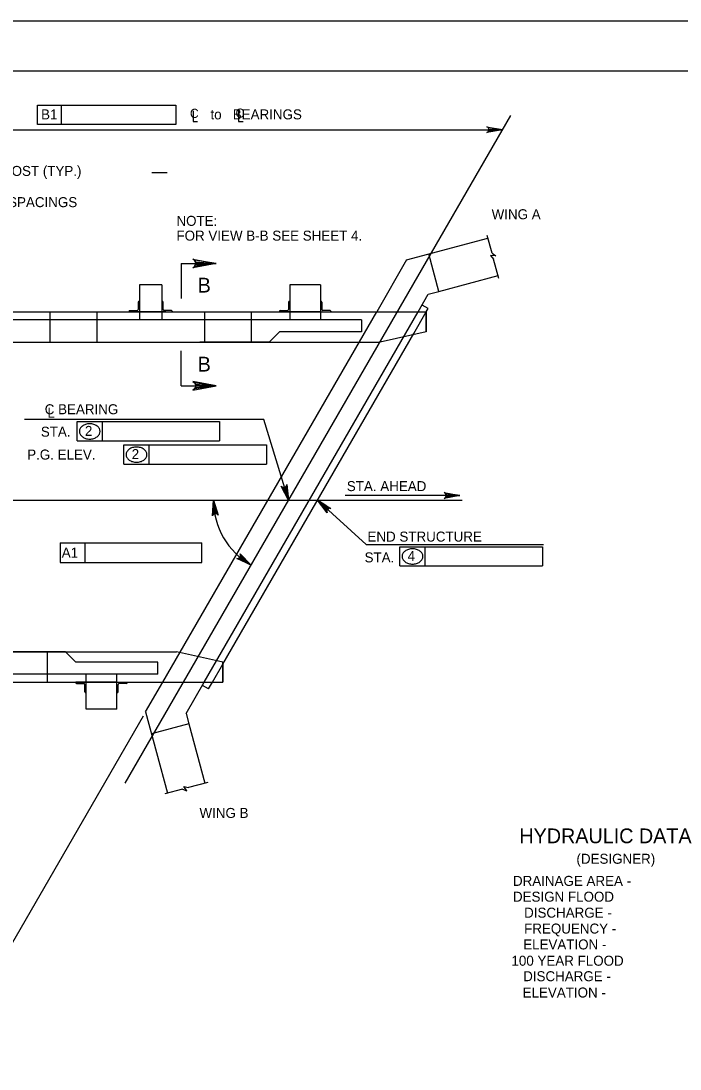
# Model space of a CAD drawing. Extents: x 638263 to 640391, y 293683 to 298655.
# Drawn here: x 638691.7 to 638889.5, y 298120.9 to 298435.5 of the extents above; entities that cross this region are included whole.
import ezdxf

# ---------------------------------------------------------------- set-up
doc = ezdxf.new("R2010")
doc.units = 0
for name, color, linetype in [('2', 7, 'Continuous'), ('3', 7, 'Continuous'), ('4', 7, 'Continuous'), ('PLT-BNDY', 7, 'Continuous')]:
    doc.layers.add(name, color=color, linetype=linetype)

msp = doc.modelspace()

# ---------------------------------------------------------------- linework, layer by layer
at = {"layer": '2'}
for p, q in [((638475.46, 298420.46), (639261.46, 298420.46)), ((638807.45, 298363.76), (638831.86, 298370.3)), ((638807.45, 298363.76), (638798.47, 298348.19)), ((638817.08, 298354.29), (638814.07, 298365.53)), ((638739.81, 298362.69), (638739.81, 298352.2)), ((638739.81, 298362.69), (638750.3, 298362.69)), ((638817.08, 298354.29), (638834.87, 298359.05)), ((638733.99, 298356.28), (638727.26, 298356.28)), ((638727.26, 298356.28), (638727.26, 298345.79)), ((638733.99, 298356.28), (638733.99, 298345.79)), ((638781.61, 298356.28), (638772.37, 298356.28)), ((638772.37, 298356.28), (638772.37, 298345.79)), ((638781.61, 298356.28), (638781.61, 298345.79)), ((638813.93, 298353.44), (638817.08, 298354.29)), ((638726.9, 298351.1), (638726.9, 298348.91)), ((638727.08, 298351.28), (638727.26, 298351.28)), ((638727.26, 298351.28), (638727.26, 298348.19)), ((638734.17, 298351.28), (638733.99, 298351.28)), ((638733.99, 298351.28), (638733.99, 298348.19)), ((638734.35, 298351.1), (638734.35, 298348.91)), ((638772.01, 298351.1), (638772.01, 298348.91)), ((638772.19, 298351.28), (638772.37, 298351.28)), ((638772.37, 298351.28), (638772.37, 298348.19)), ((638781.79, 298351.28), (638781.61, 298351.28)), ((638781.61, 298351.28), (638781.61, 298348.19)), ((638781.97, 298351.1), (638781.97, 298348.91)), ((638810.9, 298348.19), (638813.93, 298353.44)), ((638666.26, 298348.19), (638813.35, 298348.19)), ((638700.43, 298348.19), (638700.43, 298339.07)), ((638714.46, 298348.19), (638714.46, 298339.07)), ((638724.17, 298348.37), (638724.17, 298348.19)), ((638727.26, 298348.19), (638724.17, 298348.19)), ((638724.35, 298348.55), (638726.53, 298348.55)), ((638735.24, 298348.19), (638726.01, 298348.19)), ((638733.99, 298348.19), (638727.26, 298348.19)), ((638733.99, 298348.19), (638737.08, 298348.19)), ((638734.28, 298237.01), (638798.47, 298348.19)), ((638736.9, 298348.55), (638734.72, 298348.55)), ((638737.08, 298348.37), (638737.08, 298348.19)), ((638746.71, 298237.01), (638810.9, 298348.19)), ((638746.8, 298348.19), (638746.8, 298339.07)), ((638760.82, 298348.19), (638760.82, 298339.07)), ((638769.28, 298348.37), (638769.28, 298348.19)), ((638772.37, 298348.19), (638769.28, 298348.19)), ((638769.46, 298348.55), (638771.64, 298348.55)), ((638781.61, 298348.19), (638772.37, 298348.19)), ((638781.61, 298348.19), (638784.7, 298348.19)), ((638784.52, 298348.55), (638782.34, 298348.55)), ((638784.7, 298348.37), (638784.7, 298348.19)), ((638809.62, 298341.71), (638813.35, 298348.18)), ((638813.91, 298349.15), (638812.06, 298350.21)), ((638813.35, 298348.18), (638813.91, 298349.15)), ((638813.35, 298342.16), (638813.35, 298348.19)), ((638813.35, 298348.19), (638813.35, 298342.16)), ((638793.93, 298345.79), (638666.09, 298345.79)), ((638793.93, 298345.79), (638793.93, 298342.16)), ((638752.28, 298242.4), (638809.62, 298341.71)), ((638766.2, 298339.07), (638769.29, 298342.16)), ((638793.93, 298342.16), (638769.29, 298342.16)), ((638813.35, 298342.16), (638799.5, 298339.07)), ((638648.64, 298339.07), (638799.5, 298339.07)), ((638766.2, 298339.07), (638745.42, 298339.07)), ((638739.81, 298325.96), (638739.81, 298336.44)), ((638739.81, 298325.96), (638750.3, 298325.96)), ((638587.55, 298246.13), (638738.41, 298246.13)), ((638705.11, 298246.13), (638688.95, 298246.13)), ((638699.73, 298237.01), (638699.73, 298246.13)), ((638705.11, 298246.13), (638708.2, 298243.04)), ((638750.09, 298243.53), (638738.41, 298246.13)), ((638732.84, 298243.04), (638708.2, 298243.04)), ((638732.84, 298239.41), (638732.84, 298243.04)), ((638749.17, 298237.01), (638752.28, 298242.4)), ((638752.26, 298243.04), (638750.09, 298243.53)), ((638752.26, 298237.01), (638752.26, 298243.04)), ((638752.26, 298242.4), (638752.26, 298237.01)), ((638752.28, 298242.4), (638752.28, 298237.01)), ((638732.84, 298239.41), (638605, 298239.41)), ((638711.28, 298228.92), (638711.28, 298239.41)), ((638720.52, 298228.92), (638720.52, 298239.41)), ((638540.4, 298237.01), (638752.28, 298237.01)), ((638605.17, 298237.01), (638752.26, 298237.01)), ((638708.19, 298236.83), (638708.19, 298237.01)), ((638711.28, 298237.01), (638708.19, 298237.01)), ((638708.37, 298236.65), (638710.55, 298236.65)), ((638710.92, 298234.1), (638710.92, 298236.29)), ((638720.52, 298237.01), (638711.28, 298237.01)), ((638711.28, 298233.92), (638711.28, 298237.01)), ((638720.52, 298233.92), (638720.52, 298237.01)), ((638720.52, 298237.01), (638723.61, 298237.01)), ((638720.88, 298234.1), (638720.88, 298236.29)), ((638723.43, 298236.65), (638721.25, 298236.65)), ((638723.61, 298236.83), (638723.61, 298237.01)), ((638729.14, 298228.11), (638734.28, 298237.01)), ((638741.31, 298227.66), (638746.71, 298237.01)), ((638748, 298234.99), (638746.16, 298236.06)), ((638748, 298234.99), (638749.17, 298237.01)), ((638711.1, 298233.92), (638711.28, 298233.92)), ((638720.7, 298233.92), (638720.52, 298233.92)), ((638720.52, 298228.92), (638711.28, 298228.92)), ((638729.14, 298228.11), (638735.68, 298203.71)), ((638741.31, 298227.66), (638742.15, 298224.51)), ((638742.15, 298224.51), (638730.91, 298221.5)), ((638742.15, 298224.51), (638746.92, 298206.72))]:
    msp.add_line(p, q, dxfattribs=at)
for points in [[(638750.3, 298362.69), (638743.31, 298361.38), (638743.85, 298361.75), (638744.12, 298362.22), (638744.2, 298362.69), (638744.12, 298363.16), (638743.85, 298363.63), (638743.31, 298364), (638750.3, 298362.69), (638743.85, 298363.63), (638744.12, 298363.16), (638750.3, 298362.69), (638744.2, 298362.69), (638744.12, 298362.22), (638750.3, 298362.69), (638743.85, 298361.75)], [(638750.3, 298325.96), (638743.31, 298327.27), (638743.85, 298326.9), (638744.12, 298326.43), (638744.2, 298325.96), (638744.12, 298325.49), (638743.85, 298325.02), (638743.31, 298324.65), (638750.3, 298325.96), (638743.85, 298325.02), (638744.12, 298325.49), (638750.3, 298325.96), (638744.2, 298325.96), (638744.12, 298326.43), (638750.3, 298325.96), (638743.85, 298326.9)]]:
    msp.add_lwpolyline(points, dxfattribs=at)
for centre, radius, start, end in [((638727.08, 298351.1), 0.182, 90, 179.9984), ((638734.17, 298351.1), 0.182, 0.0016, 90), ((638772.19, 298351.1), 0.182, 90, 179.9984), ((638781.79, 298351.1), 0.182, 0.0016, 90), ((638724.35, 298348.37), 0.182, 90, 179.9984), ((638726.53, 298348.91), 0.364, 270, 359.9984), ((638734.72, 298348.91), 0.364, 180.0016, 270), ((638736.9, 298348.37), 0.182, 0.0016, 90), ((638769.46, 298348.37), 0.182, 90, 179.9984), ((638771.64, 298348.91), 0.364, 270, 359.9984), ((638782.34, 298348.91), 0.364, 180.0016, 270), ((638784.52, 298348.37), 0.182, 0.0016, 90), ((638708.37, 298236.83), 0.182, 180.0016, 270), ((638710.55, 298236.29), 0.364, 0.0016, 90), ((638721.25, 298236.29), 0.364, 90, 179.9984), ((638723.43, 298236.83), 0.182, 270, 359.9984), ((638711.1, 298234.1), 0.182, 180.0016, 270), ((638720.7, 298234.1), 0.182, 270, 359.9984)]:
    msp.add_arc(centre, radius, start, end, dxfattribs=at)
at = {"layer": '3'}
for p, q in [((638722.98, 298206.67), (638838.69, 298407.1)), ((638833.08, 298365.76), (638831.65, 298371.09)), ((638832.61, 298365.03), (638833.54, 298364.02)), ((638834.17, 298364.94), (638832.61, 298365.03)), ((638833.08, 298365.76), (638834.17, 298364.94)), ((638835.1, 298358.18), (638833.54, 298364.02)), ((638747.79, 298206.96), (638741.96, 298205.39)), ((638740.22, 298204.93), (638734.88, 298203.5)), ((638740.22, 298204.93), (638741.48, 298204.39)), ((638741.48, 298204.39), (638740.62, 298205.69)), ((638740.62, 298205.69), (638741.96, 298205.39))]:
    msp.add_line(p, q, dxfattribs=at)
at = {"layer": '4'}
for p, q in [((638696.71, 298410.17), (638703.94, 298410.17)), ((638696.71, 298404.4), (638696.71, 298410.17)), ((638703.94, 298404.4), (638703.94, 298410.17)), ((638703.94, 298410.17), (638738.23, 298410.17)), ((638738.23, 298410.17), (638738.23, 298404.4)), ((638743.4, 298408.45), (638743.4, 298405.26)), ((638757.04, 298408.45), (638757.04, 298405.26)), ((638738.23, 298404.4), (638696.71, 298404.4)), ((638743.4, 298405.26), (638744.73, 298405.26)), ((638757.04, 298405.26), (638758.38, 298405.26)), ((638644.81, 298402.81), (638836.22, 298402.81)), ((638731.01, 298389.95), (638735.65, 298389.95)), ((638764.57, 298315.83), (638692.76, 298315.83)), ((638708.59, 298315.21), (638716.16, 298315.21)), ((638708.59, 298309.44), (638708.59, 298315.21)), ((638716.16, 298309.44), (638716.16, 298315.21)), ((638716.16, 298315.21), (638751.35, 298315.21)), ((638751.35, 298315.21), (638751.35, 298309.44)), ((638772.04, 298291.65), (638764.57, 298315.83)), ((638708.59, 298309.44), (638751.35, 298309.44)), ((638722.63, 298308.24), (638730.2, 298308.24)), ((638722.63, 298302.47), (638722.63, 298308.24)), ((638730.2, 298302.47), (638730.2, 298308.24)), ((638730.2, 298308.24), (638765.39, 298308.24)), ((638765.39, 298308.24), (638765.39, 298302.47)), ((638722.63, 298302.47), (638765.39, 298302.47)), ((638539.12, 298291.65), (638824.14, 298291.65)), ((638780.71, 298291.65), (638795.32, 298278.31)), ((638823.37, 298293.05), (638789.02, 298293.05)), ((638703.46, 298278.86), (638703.45, 298272.96)), ((638703.46, 298278.86), (638711.02, 298278.86)), ((638711.02, 298272.96), (638711.02, 298278.86)), ((638711.02, 298278.86), (638745.98, 298278.86)), ((638745.98, 298272.96), (638745.98, 298278.86)), ((638795.32, 298278.31), (638848.5, 298278.31)), ((638805.42, 298277.69), (638813, 298277.69)), ((638805.42, 298271.92), (638805.42, 298277.69)), ((638813, 298271.92), (638813, 298277.69)), ((638813, 298277.69), (638848.18, 298277.69)), ((638848.18, 298277.69), (638848.18, 298271.92)), ((638703.45, 298272.96), (638745.98, 298272.96)), ((638805.42, 298271.92), (638848.18, 298271.92)), ((638728.37, 298226.78), (638683.43, 298148.94))]:
    msp.add_line(p, q, dxfattribs=at)
for points in [[(638836.22, 298402.81), (638831.56, 298401.94), (638831.92, 298402.19), (638832.1, 298402.5), (638832.15, 298402.81), (638832.1, 298403.12), (638831.92, 298403.44), (638831.56, 298403.68), (638836.22, 298402.81), (638831.92, 298403.44), (638832.1, 298403.12), (638836.22, 298402.81), (638832.15, 298402.81), (638832.1, 298402.5), (638836.22, 298402.81), (638831.92, 298402.19)], [(638772.04, 298291.65), (638769.83, 298295.84), (638770.17, 298295.57), (638770.52, 298295.49), (638770.84, 298295.53), (638771.12, 298295.67), (638771.37, 298295.94), (638771.5, 298296.36), (638772.04, 298291.65), (638771.37, 298295.94), (638771.12, 298295.67), (638772.04, 298291.65), (638770.84, 298295.53), (638770.52, 298295.49), (638772.04, 298291.65), (638770.17, 298295.57)], [(638749.5, 298291.65), (638750.93, 298287.13), (638750.64, 298287.45), (638750.31, 298287.6), (638749.99, 298287.61), (638749.69, 298287.52), (638749.4, 298287.3), (638749.2, 298286.92), (638749.5, 298291.65), (638749.4, 298287.3), (638749.69, 298287.52), (638749.5, 298291.65), (638749.99, 298287.61), (638750.31, 298287.6), (638749.5, 298291.65), (638750.64, 298287.45)], [(638780.71, 298291.65), (638784.74, 298289.15), (638784.31, 298289.21), (638783.96, 298289.1), (638783.71, 298288.91), (638783.54, 298288.64), (638783.47, 298288.28), (638783.56, 298287.86), (638780.71, 298291.65), (638783.47, 298288.28), (638783.54, 298288.64), (638780.71, 298291.65), (638783.71, 298288.91), (638783.96, 298289.1), (638780.71, 298291.65), (638784.31, 298289.21)], [(638823.37, 298293.05), (638818.71, 298292.18), (638819.07, 298292.43), (638819.26, 298292.74), (638819.31, 298293.05), (638819.26, 298293.36), (638819.07, 298293.68), (638818.71, 298293.92), (638823.37, 298293.05), (638819.07, 298293.68), (638819.26, 298293.36), (638823.37, 298293.05), (638819.31, 298293.05), (638819.26, 298292.74), (638823.37, 298293.05), (638819.07, 298292.43)], [(638760.77, 298272.13), (638756.48, 298274.15), (638756.91, 298274.14), (638757.24, 298274.28), (638757.47, 298274.51), (638757.61, 298274.79), (638757.64, 298275.15), (638757.5, 298275.56), (638760.77, 298272.13), (638757.64, 298275.15), (638757.61, 298274.79), (638760.77, 298272.13), (638757.47, 298274.51), (638757.24, 298274.28), (638760.77, 298272.13), (638756.91, 298274.14)]]:
    msp.add_lwpolyline(points, dxfattribs=at)
for points in [[(638771.64, 298294.61), (638770.69, 298294.32), (638772.04, 298291.65)], [(638782.56, 298289.29), (638783.22, 298290.02), (638780.71, 298291.65)]]:
    msp.add_lwpolyline(points, close=True, dxfattribs=at)
for centre, radius, start, end in [((638711.64, 298311.9), 2.49, 126.3544, 150.6308), ((638712.08, 298311.3), 3.23, 106.9552, 126.3544), ((638712.37, 298310.35), 4.22, 90, 106.9552), ((638712.37, 298310.35), 4.22, 73.0448, 90), ((638712.66, 298311.3), 3.23, 53.6456, 73.0448), ((638713.1, 298311.9), 2.49, 29.3692, 53.6456), ((638710.96, 298312.28), 1.71, 150.6308, 180), ((638710.96, 298312.28), 1.71, 180, 209.3692), ((638711.64, 298312.66), 2.49, 209.3692, 233.6456), ((638712.08, 298313.26), 3.23, 233.6456, 253.0448), ((638712.37, 298314.2), 4.22, 253.0448, 270), ((638712.37, 298314.2), 4.22, 270, 286.9552), ((638712.66, 298313.26), 3.23, 286.9552, 306.3544), ((638713.1, 298312.66), 2.49, 306.3544, 330.6308), ((638713.78, 298312.28), 1.71, 0, 29.3692), ((638713.78, 298312.28), 1.71, 330.6308, 0), ((638725.68, 298304.93), 2.49, 126.3544, 150.6308), ((638726.12, 298304.33), 3.23, 106.9552, 126.3544), ((638726.41, 298303.38), 4.22, 90, 106.9552), ((638726.41, 298303.38), 4.22, 73.0448, 90), ((638726.7, 298304.33), 3.23, 53.6456, 73.0448), ((638727.14, 298304.93), 2.49, 29.3692, 53.6456), ((638725, 298305.31), 1.71, 150.6308, 180), ((638725, 298305.31), 1.71, 180, 209.3692), ((638725.68, 298305.69), 2.49, 209.3692, 233.6456), ((638727.14, 298305.69), 2.49, 306.3544, 330.6308), ((638727.82, 298305.31), 1.71, 0, 29.3692), ((638727.82, 298305.31), 1.71, 330.6308, 0), ((638726.12, 298306.29), 3.23, 233.6456, 253.0448), ((638726.41, 298307.24), 4.22, 253.0448, 270), ((638726.41, 298307.24), 4.22, 270, 286.9552), ((638726.7, 298306.29), 3.23, 286.9552, 306.3544), ((638772.04, 298291.65), 22.54, 179.9993, 239.9995), ((638807.8, 298274.76), 1.71, 150.6308, 180), ((638808.47, 298274.38), 2.49, 126.3544, 150.6308), ((638808.92, 298273.78), 3.23, 106.9552, 126.3544), ((638809.2, 298272.83), 4.22, 90, 106.9552), ((638809.2, 298272.83), 4.22, 73.0448, 90), ((638809.49, 298273.78), 3.23, 53.6456, 73.0448), ((638809.93, 298274.38), 2.49, 29.3692, 53.6456), ((638810.61, 298274.76), 1.71, 0, 29.3692), ((638807.8, 298274.76), 1.71, 180, 209.3692), ((638808.47, 298275.14), 2.49, 209.3692, 233.6456), ((638808.92, 298275.74), 3.23, 233.6456, 253.0448), ((638809.2, 298276.69), 4.22, 253.0448, 270), ((638809.2, 298276.69), 4.22, 270, 286.9552), ((638809.49, 298275.74), 3.23, 286.9552, 306.3544), ((638809.93, 298275.14), 2.49, 306.3544, 330.6308), ((638810.61, 298274.76), 1.71, 330.6308, 0)]:
    msp.add_arc(centre, radius, start, end, dxfattribs=at)
at = {"layer": 'PLT-BNDY'}
msp.add_lwpolyline([(638435.46, 298435.46), (639276.46, 298435.46), (639276.46, 297841.46), (638435.46, 297841.46)], close=True, dxfattribs=at)

# ---------------------------------------------------------------- texts
at = {"layer": '4'}
for s, height, p in [('B1', 3, (638697.77, 298405.92)), ('C', 2.73, (638742.43, 298406.36)), ('to   BEARINGS', 3, (638748.6, 298405.92)), ('C', 2.73, (638756.11, 298406.43)), ('GLULAM BRIDGE RAIL POST (TYP.)', 3, (638642.12, 298388.95)), ('FOR DIMENSIONS AND SPACINGS', 3, (638642.19, 298379.58)), ('NOTE:', 3, (638738.39, 298373.97)), ('WING A', 3, (638832.95, 298375.95)), ('FOR VIEW B-B SEE SHEET 4.', 3, (638738.39, 298369.53)), ('B', 4.43, (638744.76, 298330.25)), ('C BEARING', 3, (638698.87, 298317.43)), ('L', 3, (638699.69, 298316.38)), ('STA.', 3, (638697.7, 298310.69)), ('2', 3, (638710.92, 298310.93)), ('2', 3, (638724.96, 298303.96)), ('P.G. ELEV.', 3, (638693.6, 298303.83)), ('STA. AHEAD', 3, (638789.51, 298294.36)), ('END STRUCTURE', 3, (638795.7, 298279.21)), ('STA.', 3, (638794.83, 298272.97)), ('4', 3, (638807.75, 298273.41)), ('WING B', 3, (638745.3, 298196.28)), ('HYDRAULIC DATA', 4.4292, (638841.27, 298188.69)), ('(DESIGNER)', 3, (638858.4, 298182.53)), ('DRAINAGE AREA - ', 3, (638839.35, 298175.89)), ('DESIGN FLOOD  ', 3, (638839.35, 298171.15)), ('   DISCHARGE - ', 3, (638839.35, 298166.35)), ('   FREQUENCY - ', 3, (638839.35, 298161.58)), ('   ELEVATION - ', 3, (638839.07, 298156.82)), ('100 YEAR FLOOD', 3, (638838.9, 298151.93)), ('   DISCHARGE - ', 3, (638839.07, 298147.28)), ('   ELEVATION - ', 3, (638838.9, 298142.39))]:
    msp.add_text(s, height=height, dxfattribs=at).set_placement(p)
for s, height, rotation, p in [('B', 4.43, 360, (638744.76, 298353.96)), ('A1', 3, 359.9382, (638703.97, 298274.41))]:
    msp.add_text(s, height=height, rotation=rotation, dxfattribs=at).set_placement(p)

doc.saveas('drawing.dxf')
